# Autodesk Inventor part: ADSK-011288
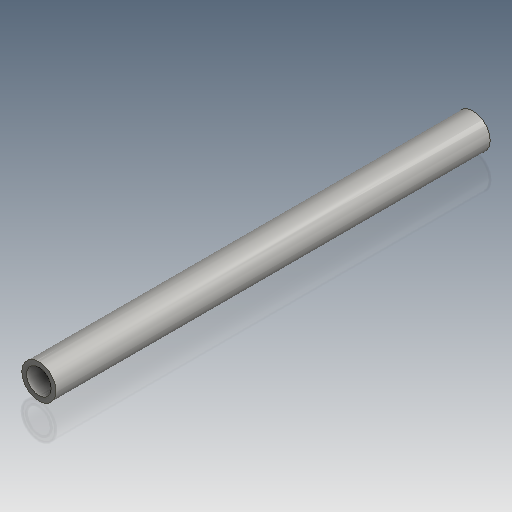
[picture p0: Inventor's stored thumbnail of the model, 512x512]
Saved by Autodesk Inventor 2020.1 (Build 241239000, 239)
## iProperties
Created: 1999-12
Part Number: ADSK-011288
Document SubType Name: Modeling
Designer: glanglot
Material: Pearson HRS
Density: 7.83 g/cm^3
Appearance: Steel
Mass: 1372.96 g
Surface Area: 779.573 cm^2
Volume: 175.347 cm^3
Control State: 0
Master: False
Checked Out: False
Shininess: 25.0
Length Units: 11272
Angle Units: 11279
Time Units: 11290
Mass Units: 11286
Length Display Precision: 3
Angle Display Precision: 2
Compacted: True
Cutlength: 16.75
Material Desc: PIPE,BLACK,SCH-80,01.0000
Material_Number: A084534
Dimensions: 1,3x1,3x16,8 in
Mass: 3,027 lb
DocNumber: ADSK-011288.ipt
Folder: 01 - Themengebiete\Simplification\01 - Packaging machine\
VDS_Category: 3D Komponenten
Density: 7.830000000000001
Volumn: 175.34653823645593
Area: 779.573267031743
PropertySet Name: Model Information
Author: glanglot
Revision Number: -
Title: base plate
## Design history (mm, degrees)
node "Extrusion1" dims "d2" = 425.45, "d3" = 0
node "Solide1"
node "Corps solides"
node "Corps surfaciques"
sketch "Sketch1"
  geometry: C1 r 16.7 at (0, 0); C2 r 12.154 at (0, 0)
  constraints: 2 centre point
  dimensions: "d0" = 33.401 diameter of C1; "d1" = 4.5466 radial gap between concentric circles of C1 C2
